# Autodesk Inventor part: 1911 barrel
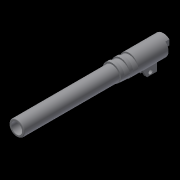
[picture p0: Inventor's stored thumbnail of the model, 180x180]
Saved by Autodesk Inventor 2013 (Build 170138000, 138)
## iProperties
Created: 2013-01
Part Number: 1911 barrel
Material: Generic
Document SubType Name: Modeling
Designer: John
Density: 1 g/cm^3
Author: John
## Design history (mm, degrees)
sketch "Sketch1"
  geometry: C1 r 7.366 at (0, 0); C2 r 5.613 at (0, 0); 1 further point
  constraints: 2 centre point, 2 coincident
  dimensions: "d21" = 11.2268 diameter of C2; "d23" = 14.732 diameter of C1
extrude "Extrusion1" new body sketch "Sketch1" distance "d2" = 76.3016; taper "d3" = 0 deg
sketch "Sketch2"
  geometry: C1 r 5.613 at (0, 0) reference; C2 r 8.839 at (0, 0)
  constraints: 1 centre point
extrude "Extrusion2" join sketch "Sketch2" distance "d5" = 51.4858; taper "d6" = 0 deg
sketch "Sketch3"
  geometry: C1 r 5.613 at (0, 0) reference; C2 r 8.839 at (0, 0) reference; C3 r 6.02 at (0, 0)
  constraints: 1 centre point, 1 coincident
  dimensions: "d11" = 12.0396 diameter of C3
extrude "Extrusion3" cut sketch "Sketch3" distance "d12" = 22.6568; taper "d13" = 0 deg
sketch "Sketch4"
  geometry: L1 (-5.844, 1.442)-(-5.844, 6.631); L2 (5.766, 1.73)-(5.766, 6.7); A1 r 6.02 centre (0, 0) between (-5.844, 1.442) and (5.766, 1.73) reference; A2 r 8.839 centre (0, 0) between (-5.844, 6.631) and (5.766, 6.7) reference
  constraints: 4 end point, 4 point on circle
extrude "Extrusion4" cut sketch "Sketch4" distance "d16" = 3.7846; taper "d17" = 0 deg
workplane "Work Plane1"
sketch "Sketch6"
  geometry: A1 r 8.839 centre (0, 0) between (8.839, 0) and (-8.839, 0) reference; A2 r 8.987 centre (0, -1.621) between (8.839, 0) and (-8.839, 0); 1 further point
  constraints: 4 point on circle, 1 centre point
extrude "Extrusion5" cut sketch "Sketch6" distance "d26" = 4.4704; taper "d27" = 0 deg
workplane "Work Plane2"
pattern_linear "Rectangular Pattern1" dims "d31" = 8.2296
sketch "Sketch7"
  geometry: A1 r 7.874 centre (0, 0.127) between (-6.718, -3.981) and (6.718, -3.981); A2 r 45.966 centre (45.601, -28.495) between (8.786, -0.972) and (6.62, -4.137); A3 r 45.966 centre (-45.601, -28.495) between (-6.62, -4.137) and (-8.786, -0.972); A4 r 8.839 centre (0, 0) between (-8.786, -0.972) and (8.786, -0.972)
  constraints: 11 point on circle, 4 centre point
workplane "Work Plane3"
sketch "Sketch8"
  geometry: A1 r 7.874 centre (0, -0.965) between (-6.718, -5.073) and (6.718, -5.073); A2 r 45.966 centre (45.601, -29.587) between (8.786, -2.065) and (6.718, -5.073); A3 r 45.966 centre (-45.601, -29.587) between (-6.62, -5.229) and (-8.786, -2.065); A4 r 8.839 centre (0, -1.092) between (-8.786, -2.065) and (8.786, -2.065); 1 further point
  constraints: 11 point on circle, 4 centre point
loft "Loft1" sketch "Sketch8" dims "d38" = 0, "d39" = 90 deg, "d40" = 0, "d41" = 90 deg
sketch "Sketch9"
  geometry: L1 (6.7, -127.787)-(8.839, -127.787) reference; L2 (-6.02, -124.003)-(-6.02, -105.131) reference; L3 (-6.02, -117.462)-(-15.474, -117.462) reference; L4 (-1.992, -100.28)-(19.263, -100.28); L5 (-6.02, -102.467)-(-14.837, -107.254); L6 (-6.02, -117.462)-(-6.02, -102.467); L7 (-15.474, -117.462)-(-15.474, -107.677); C1 r 1.956 at (-12.776, -111.049) reference; A1 r 4.318 centre (-12.776, -111.049) between (-14.837, -107.254) and (-15.474, -107.677) reference; 2 further points
  constraints: 10 end point, 2 centre point, 2 horizontal, 2 point on circle, 1 coincident, 1 perpendicular, 1 point on line, 1 tangent, 2 other
extrude "Extrusion6" join sketch "Sketch9" stored distance "d52" = 9.1948; taper "d53" = 0 deg
sketch "Sketch11"
  geometry: L1 (-8.839, -103.998)-(-8.839, -98.66) reference; C1 r 1.956 at (-12.776, -111.049) reference; 2 further points
  constraints: 2 end point, 1 vertical, 3 other
extrude "Extrusion8" cut sketch "Sketch11" stored distance "d59" = 3.5052; taper "d60" = 0 deg
fillet "Fillet1" dims "d61" = 1.524
chamfer "Chamfer1" distance "d62" = 0.381; stored, may be unused: second distance "d63" = 3.175, angle "d64" = 45 deg
sketch "Sketch12"
  geometry: C1 r 12.816 at (0, 0); C2 r 7.366 at (0, 0) reference
  constraints: 1 centre point
extrude "Extrusion9" cut sketch "Sketch12" stored distance "d66" = 25.4; taper "d67" = 0 deg
sketch "Sketch14"
  geometry: L1 (-6.02, -124.003)-(-6.02, -105.131) reference; L2 (-12.776, -111.049)-(-31.276, -124.003); L3 (-12.776, -111.049)-(9.808, -111.049); L4 (-31.276, -124.003)-(-23.817, -134.656); L5 (-8.839, -89.078)-(-8.839, -124.003) reference; L6 (-4.764, -113.673)-(-0.108, -115.368); L7 (-0.108, -115.368)-(-6.685, -133.438); L8 (-6.685, -133.438)-(-11.341, -131.743); L9 (-4.764, -113.673)-(-11.341, -131.743); C1 r 1.956 at (-12.776, -111.049) reference; 1 further point
  constraints: 14 end point, 2 perpendicular, 1 equal length, 1 horizontal, 1 parallel
  dimensions: "d74" = 145 deg angle of L2 L3; "d75" = 13.0048 distance of L2.end L4.end
sketch "Sketch15"
  geometry: C1 r 5.5 at (0, 0); C2 r 6.02 at (0, 0); A1 r 6.02 centre (0, 0) between (-5.844, 1.442) and (5.766, 1.73) reference; A2 r 6.02 centre (0, 0) between (5.766, 1.73) and (-5.844, 1.442) reference
  constraints: 2 centre point, 2 coincident, 1 concentric
  dimensions: "d77" = 11 diameter of C1
extrude "Extrusion11" join sketch "Sketch15" stored distance "d78" = 25.4; taper "d79" = 0 deg
workplane "Work Plane4"
sketch "Sketch16"
  geometry: C1 r 5.613 at (0, 0) reference; C2 r 6.604 at (0, 0) reference; C3 r 5.207 at (0, 0)
  constraints: 1 centre point, 1 coincident
  dimensions: "d80" = 10.414 diameter of C3
extrude "Extrusion12" join sketch "Sketch16" stored distance "d81" = 25.4; taper "d82" = 0 deg
revolve "Revolution3" stored, may be unused: angle "d85" = 90 deg
sketch "Sketch17"
  geometry: C1 r 7.366 at (0, 0) reference; A1 r 8.839 centre (0, 0) between (8.761, -1.175) and (-8.761, -1.175) reference; A2 r 45.966 centre (-45.601, -28.664) between (-6.718, -4.15) and (-8.761, -1.175) reference; A3 r 7.874 centre (0, -0.042) between (-6.718, -4.15) and (6.718, -4.15) reference; A4 r 45.966 centre (45.601, -28.664) between (8.761, -1.175) and (6.718, -4.15) reference
extrude "Extrusion13" cut sketch "Sketch17" distance "d86" = 0.254; taper "d87" = 0 deg
sketch "Sketch18"
  geometry: A1 r 8.839 centre (0, 0) between (8.839, 0) and (-8.839, 0) reference; A2 r 8.987 centre (0, -1.621) between (8.839, 0) and (-8.839, 0) reference
extrude "Extrusion14" cut sketch "Sketch18" distance "d88" = 0.254; taper "d89" = 0 deg
sketch "Sketch19"
  geometry: A1 r 8.839 centre (0, 1.621) between (8.839, 1.621) and (-8.839, 1.621) reference; A2 r 8.987 centre (0, 0) between (8.839, 1.621) and (-8.839, 1.621) reference
extrude "Extrusion15" cut sketch "Sketch19" distance "d90" = 0.254; taper "d91" = 0 deg
sketch "Sketch20"
  geometry: A1 r 8.839 centre (0, 0) between (8.839, 0) and (-8.839, 0) reference; A2 r 8.987 centre (0, -1.621) between (8.839, 0) and (-8.839, 0) reference
extrude "Extrusion16" cut sketch "Sketch20" distance "d92" = 0.254; taper "d93" = 0 deg
sketch "Sketch21"
  geometry: A1 r 8.839 centre (0, 0) between (8.839, 0) and (-8.839, 0) reference; A2 r 8.987 centre (0, -1.621) between (8.839, 0) and (-8.839, 0) reference
extrude "Extrusion17" cut sketch "Sketch21" distance "d94" = 0.254; taper "d95" = 0 deg
sketch "Sketch22"
  geometry: C1 r 5.207 at (0, 0) reference; C2 r 7.366 at (0, 0) reference
extrude "Extrusion18" join sketch "Sketch22" distance "d96" = 12.7; taper "d97" = 0 deg
fillet "Fillet3" dims "d98" = 0.79375
sketch "Sketch23"
  geometry: C1 r 5.625 at (0, 0); A1 r 5.5 centre (0, 0) between (4.903, -2.491) and (-4.903, -2.491) reference
  constraints: 1 centre point, 1 coincident
  dimensions: "d99" = 11.25 diameter of C1
extrude "Extrusion19" cut sketch "Sketch23" stored distance "d102" = 12.7; taper "d103" = 0 deg
sketch "Sketch24"
  geometry: C1 r 6.02 at (0, 0); C2 r 5.715 at (0, 0); A1 r 6.02 centre (0, 0) between (5.766, 1.73) and (-5.844, 1.442) reference; A2 r 5.625 centre (0, 0) between (4.929, -2.71) and (-4.929, -2.71) reference
  constraints: 2 centre point, 2 coincident, 1 concentric
  dimensions: "d104" = 11.43 diameter of C2
extrude "Extrusion20" cut sketch "Sketch24" stored distance "d105" = 20.583; taper "d106" = 0 deg
sketch "Sketch25"
  geometry: L1 (5.766, 1.73)-(5.766, 6.7) reference; L2 (4.617, 3.863)-(5.766, 4.322); A1 r 6.02 centre (0, 0) between (5.766, 1.73) and (-5.844, 1.442) reference
  constraints: 2 end point, 1 point on circle, 1 point on line
extrude "Extrusion21" cut sketch "Sketch25" stored distance "d107" = 25.4; taper "d108" = 0 deg
body "Solid1"
other parameters: "d18" = -29.2608, "d28" = -37.4904, "d37" = -34.925, "d50" = 151.5 deg
